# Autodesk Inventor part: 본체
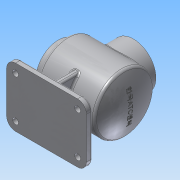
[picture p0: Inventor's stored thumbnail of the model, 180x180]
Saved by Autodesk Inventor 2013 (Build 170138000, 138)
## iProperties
Created: 2016-09
Part Number: 본체
Material: 알루미늄 6061
Document SubType Name: Modeling
Designer: Administrator
Density: 2.71 g/cm^3
Mass: 972.437 g
Surface Area: 1283.07 cm^2
Volume: 358.833 cm^3
Author: Administrator
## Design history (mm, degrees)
sketch "스케치1"
  geometry: L1 (-62, 0)-(60, 0); L2 (48.562, 50)-(-50, 50); L3 (-50, 50)-(-50, 38); L4 (-50, 38)-(-62, 38); L5 (-62, 38)-(-62, 0); L6 (-47, 27)-(-47, 47); L7 (-47, 47)-(46.661, 47); L8 (-47, 27)-(-62, 27); A1 r 115 centre (-55, 0) between (60, 0) and (48.562, 50); A2 r 112 centre (-55, 0) between (57, 0) and (46.661, 47); 1 further point
  constraints: 16 end point, 4 point on circle, 3 parallel, 3 point on line, 2 centre point, 2 horizontal, 2 horizontal alignment, 1 perpendicular, 1 other
  dimensions: "d0" = 122 distance of L1.start L1.end; "d2" = 110 distance from line of L1.end L3; "d3" = 115 radius of A1; "d4" = 100 diameter of L2 L1; "d5" = 76 diameter of L4 L1; "d6" = 62 distance from line of point (0, 0) L5; "d7" = 94 diameter of L7 L1; "d8" = 3 radial gap between concentric circles of A2 A1; "d10" = 54 diameter of L8 L1
revolve "회전1" sketch "스케치1" stored, may be unused: angle "d11" = 90 deg
node "작업 평면1"
sketch "스케치2"
  geometry: L1 (67.5, -50)-(-67.5, -50); L2 (-67.5, -50)-(-67.5, 50); L3 (-67.5, 50)-(67.5, 50); L4 (67.5, 50)-(67.5, -50); 1 further point
  constraints: 8 end point, 2 parallel, 1 horizontal, 1 perpendicular
  dimensions: "d13" = 135 distance of L1.start L1.end; "d15" = 100 distance of L3.end L1.start; "d16" = 67.5 distance from line of point (0, 0) L4; "d17" = 50 distance from line of L1 point (0, 0)
extrude "돌출1" join sketch "스케치2" distance "d18" = 10; taper "d19" = 0 deg
fillet "모깎기1" dims "d20" = 15
sketch "스케치3"
  geometry: L1 (-5, 40)-(5, 40); L2 (5, 40)-(5, -40); L3 (5, -40)-(-5, -40); L4 (-5, -40)-(-5, 40); 3 further points
  constraints: 8 end point, 2 midpoint, 2 parallel, 1 horizontal, 1 horizontal alignment, 1 perpendicular, 1 vertical alignment
  dimensions: "d21" = 10 distance of L1.start L1.end; "d23" = 80 distance of L3.end L1.start
extrude "돌출2" join sketch "스케치3" stored distance "d24" = 10; taper "d25" = 0 deg
sketch "스케치4"
  geometry: L1 (46.661, 47)-(-47, 47) reference; L2 (-47, 47)-(-47, 27) reference; L3 (-47, 27)-(-62, 27) reference; L4 (-62, 27)-(-62, 38) reference; L5 (-62, 38)-(-50, 38) reference; L6 (-50, 38)-(-50, 50) reference; L7 (-50, 50)-(48.562, 50) reference; L8 (48.562, -50)-(5, -50) reference; L9 (5, -50)-(5, -72) reference; L10 (5, -72)-(67.5, -72) reference; L11 (67.5, -72)-(67.5, -82) reference; L12 (67.5, -82)-(-67.5, -82) reference; L13 (-67.5, -82)-(-67.5, -72) reference; L14 (-67.5, -72)-(-5, -72) reference; L15 (-5, -72)-(-5, -50) reference; L16 (-5, -50)-(-50, -50) reference; L17 (-50, -50)-(-50, -38) reference; L18 (-50, -38)-(-62, -38) reference; L19 (-62, -38)-(-62, -27) reference; L20 (-62, -27)-(-47, -27) reference; L21 (-47, -27)-(-47, -47) reference; L22 (-47, -47)-(46.661, -47) reference; L23 (-40, -72)-(-38.075, -50); L24 (38.075, -50)-(40, -72); A1 r 112 centre (-55, 0) between (46.661, -47) and (46.661, 47) reference; A2 r 115 centre (-55, 0) between (48.562, -50) and (48.562, 50) reference; 1 further point
  constraints: 4 end point, 4 point on line
  dimensions: "d26" = 40 horizontal distance of L23.start point (0, 0); "d27" = 40 horizontal distance of L24.end point (0, 0); "d28" = 95 deg angle of L23 L14; "d29" = 95 deg angle of L24 L10
  node "절단 모서리 투영1"
feature "리브1" dims "d30" = 1, "d31" = 10, "d32" = 0, "d33" = 0, "d34" = 1, "d35" = 1
feature "리브2" dims "d36" = 1, "d37" = 10, "d38" = 0, "d39" = 0, "d40" = 1, "d41" = 1
node "작업 평면2"
sketch "스케치5"
  geometry: C1 r 38 at (0, 0); 1 further point
  constraints: 1 centre point, 1 coincident
  dimensions: "d43" = 76 diameter of C1
extrude "돌출3" join sketch "스케치5" stored distance "d44" = 10; taper "d45" = 0 deg
hole "구멍1" diameter "d48" = 54; stored, may be unused: countersink angle "d52" = 90 deg, drill point angle "d54" = 0 deg; dims "d49" = 6, "d50" = 4, "d51" = 2, "d53" = 8, "d55" = 10, "d56" = 10
sketch "스케치6"
  geometry: C1 r 27 at (0, 0) reference; 1 further point
  constraints: 1 vertical alignment
  dimensions: "d57" = 32.5 distance of point (0, 32.5) C1.centre
hole "구멍2" sketch "스케치6" at (0, 32.5) diameter "d58" = 3.242; stored, may be unused: countersink angle "d62" = 90 deg, drill point angle "d64" = 118 deg; dims "d59" = 8, "d60" = 4, "d61" = 2, "d63" = 10
sketch "스케치7"
  geometry: C1 r 27 at (0, 0) reference; 1 further point
  constraints: 1 vertical alignment
  dimensions: "d68" = 32.5 distance of point (0, 32.5) C1.centre
hole "구멍3" sketch "스케치7" at (0, 32.5) diameter "d69" = 3.242; stored, may be unused: countersink angle "d73" = 90 deg, drill point angle "d75" = 118 deg; dims "d70" = 8, "d71" = 4, "d72" = 2, "d74" = 10
hole "구멍5" diameter "d90" = 10; stored, may be unused: countersink angle "d94" = 90 deg, drill point angle "d96" = 0 deg; dims "d88" = 10, "d89" = 10, "d91" = 8, "d92" = 4, "d93" = 2, "d95" = 10
fillet "모깎기2" dims "d97" = 5, "d98" = 3
fillet "모깎기3" dims "d99" = 2
fillet "모깎기4" dims "d100" = 3
chamfer "모따기1" distance "d101" = 1; stored, may be unused: second distance "d102" = 2, angle "d103" = 45 deg
node "작업 평면3"
sketch "스케치8"
  geometry: 2 further points
  constraints: 1 coincident, 1 other
feature "엠보싱1" sketch "스케치8" dims "d104" = 0.5, "d105" = 0
node "솔리드1"
pattern_circular "원형 패턴1" dims angle "d66" = 360 deg
pattern_circular "원형 패턴2" dims angle "d77" = 360 deg
mirror "대칭1"
mirror "대칭2"
other parameters: "d12" = -82, "d42" = 65
